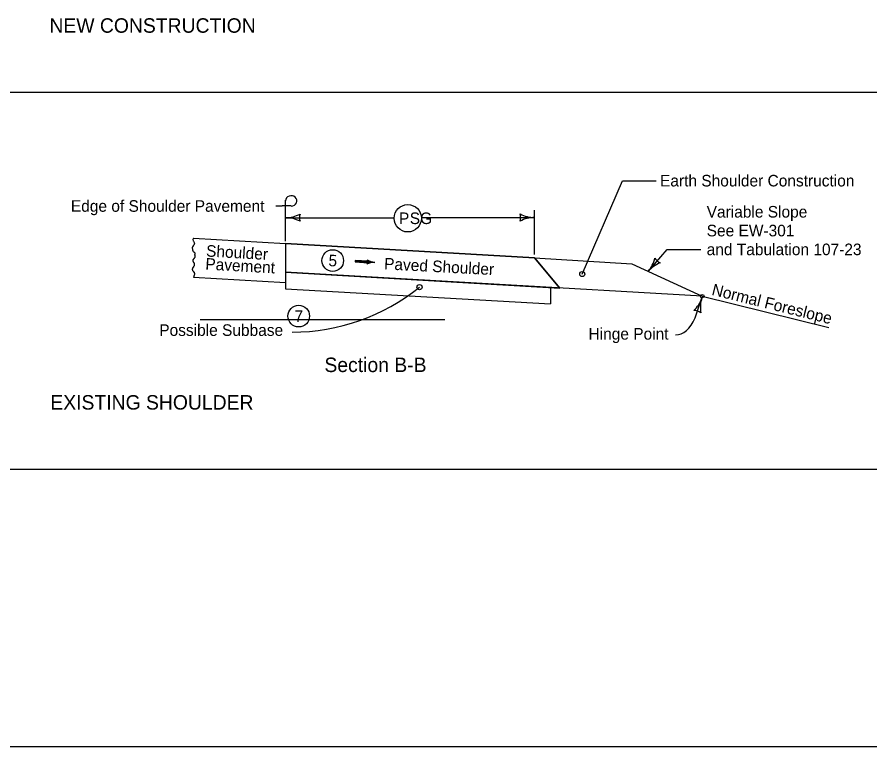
# Model space of a CAD drawing. Extents: x 6410 to 81668, y 3928 to 11667.
# Drawn here: x 11038 to 12218, y 7924 to 8933 of the extents above; entities that cross this region are included whole.
import ezdxf

# ---------------------------------------------------------------- set-up
doc = ezdxf.new("R2010")
doc.units = 0
for name, color, linetype in [('dsnCellElements', 7, 'Continuous'), ('dsnNonPlotable', 7, 'Continuous'), ('dsnShtPlotShapeBatchPrint', 7, 'Continuous'), ('dsnStdBlockModified', 7, 'Continuous'), ('Level 11', 7, 'Continuous'), ('Level 14', 7, 'Continuous'), ('Level 7', 7, 'Continuous'), ('Level 8', 7, 'Continuous')]:
    doc.layers.add(name, color=color, linetype=linetype)

msp = doc.modelspace()

# ---------------------------------------------------------------- linework, layer by layer
at = {"layer": 'dsnCellElements'}
for p, q in [((11819.9, 8577.8), (11875.6, 8706.9)), ((11875.6, 8706.9), (11922, 8706.9)), ((11396.3, 8671.9), (11405, 8671.9)), ((11417.5, 8671.9), (11405, 8671.9)), ((11409.7, 8659.1), (11409.7, 8679.9)), ((11409.7, 8623.1), (11409.7, 8659.1)), ((11910.9, 8581.5), (11937.5, 8611.9)), ((11937.5, 8611.9), (11983.9, 8611.9)), ((11524, 8594.5), (11505.8, 8595.5)), ((11523.9, 8593.5), (11523.9, 8593.5)), ((11524, 8595.5), (11524, 8595.5)), ((11976, 8517.2), (11985.5, 8544.8))]:
    msp.add_line(p, q, dxfattribs=at)
for points in [[(11524, 8595.4), (11505.8, 8596.5), (11505.7, 8594.6), (11523.9, 8593.5), (11523.9, 8595.1), (11506, 8596.2), (11506, 8594.7), (11523.5, 8593.8), (11523.6, 8594.9), (11506.3, 8596), (11506.2, 8595), (11523.3, 8594), (11523.4, 8594.7), (11506.5, 8595.8), (11506.4, 8595.2), (11523, 8594.3)], [(11523.6, 8596.7), (11524.3, 8595.5), (11524.3, 8593.9), (11523.5, 8592.5), (11526.2, 8593.3), (11529.4, 8594), (11530.3, 8594.1), (11528.1, 8594.7), (11524.9, 8595.9), (11523.9, 8596.4), (11524.1, 8592.9), (11529, 8594.1), (11524.4, 8595.7), (11524.4, 8593.3), (11527.8, 8594.2), (11524.8, 8595.1), (11524.5, 8593.7), (11526.7, 8594.2), (11525.1, 8594.7), (11525, 8594), (11525.8, 8594.2)]]:
    msp.add_lwpolyline(points, dxfattribs=at)
for centre, radius, start, end in [((11878.9, 8609.5), 42.5, 318.8454, 346.9178), ((11934.4, 8608.3), 16.4, 211.112, 246.5787), ((11942.9, 8553.5), 42.5, 110.7729, 138.8454), ((11945.3, 8558.6), 42.5, 312.9788, 341.0513), ((12025.7, 8531), 42.5, 161.0513, 189.1238), ((11973.9, 8511.1), 16.4, 53.3179, 88.7846)]:
    msp.add_arc(centre, radius, start, end, dxfattribs=at)
for centre, major_axis, ratio, start_param, end_param in [((11417.5, 8679), (-7.81, 0), 0.913811, 1.570796, 6.283185), ((11520.2, 8594.7), (3.88, 0), 0.913811, 5.202895, 7.237436), ((11532.5, 8573.7), (22.2, 0), 0.913811, 1.537172, 2.061295), ((11535.3, 8614.1), (-22.2, 0), 0.913811, 0.954258, 1.478381), ((11948.9, 8555.1), (0, 61.5), 0.559383, 3.141593, 4.048985)]:
    msp.add_ellipse(centre, major_axis=major_axis, ratio=ratio, start_param=start_param, end_param=end_param, dxfattribs=at)
at = {"layer": 'dsnNonPlotable'}
msp.add_line((10153.2, 8307.9), (13248.9, 8307.9), dxfattribs=at)
at = {"layer": 'dsnShtPlotShapeBatchPrint'}
for p, q in [((11754, 8604.6), (11754, 8666.3)), ((11409.7, 8655.7), (11559.7, 8655.7)), ((11597.5, 8655.9), (11754, 8655.9))]:
    msp.add_line(p, q, dxfattribs=at)
msp.add_circle((11578.6, 8654.9), 18.9, dxfattribs=at)
for centre, radius, start, end in [((11409.7, 8698.2), 42.5, 270, 298.0725), ((11445.3, 8655.7), 16.4, 162.2666, 197.7334), ((11718.3, 8655.9), 16.4, 342.2666, 17.7333), ((11754, 8698.4), 42.5, 241.9275, 270), ((11409.7, 8613.2), 42.5, 61.9275, 90), ((11754, 8613.4), 42.5, 90, 118.0725), ((11418.2, 8779.5), 282, 270.132, 308.7946)]:
    msp.add_arc(centre, radius, start, end, dxfattribs=at)
at = {"layer": 'dsnStdBlockModified'}
for p, q in [((11282.2, 8627.4), (11409.7, 8620)), ((11409.7, 8620), (11409.7, 8566)), ((11409.7, 8620), (11754, 8600)), ((11754, 8600), (11409.7, 8620)), ((11409.7, 8620), (11409.7, 8580.4)), ((11753.5, 8600.2), (11753.5, 8600.2)), ((11754, 8600), (11789, 8558.5)), ((11754, 8600), (11888.7, 8591.7)), ((11789, 8558.5), (11754, 8600)), ((11888.7, 8591.7), (11985.8, 8547.2)), ((11985.8, 8547.2), (11409.7, 8580.4)), ((11409.7, 8580.4), (11789, 8558.5)), ((11282.2, 8573.4), (11409.7, 8566)), ((11409.7, 8566), (11409.7, 8557.5)), ((11776.2, 8573.7), (11776.2, 8573.7)), ((11409.7, 8557.5), (11776.2, 8536.4)), ((11776.2, 8559.2), (11776.2, 8536.4)), ((11985.8, 8547.2), (12160.8, 8503.9)), ((11291.6, 8515.1), (11630.1, 8515.1))]:
    msp.add_line(p, q, dxfattribs=at)
msp.add_circle((11474.8, 8596.4), 15, dxfattribs=at)
msp.add_ellipse((11985.8, 8547.2), major_axis=(2.58, 0), ratio=0.913811, dxfattribs=at)
for points in [[(11282.2, 8627.4), (11281.7, 8623.8), (11282.8, 8622.3), (11283.6, 8620), (11283, 8617.9), (11281.1, 8615.6), (11280.6, 8613.7), (11281.1, 8611.4), (11282, 8609), (11283, 8608.3), (11284.4, 8605.7), (11284.4, 8604.9)], [(11282.4, 8587.8), (11282.6, 8588), (11282.8, 8588.3), (11283.2, 8588.8), (11283.5, 8589.4), (11283.6, 8589.7), (11283.7, 8590.1), (11283.8, 8590.7), (11283.9, 8591.3), (11283.8, 8591.9), (11283.8, 8592.2), (11283.7, 8592.3), (11283.7, 8592.4), (11283.5, 8592.8), (11283.2, 8593.2), (11282.9, 8593.5), (11282.6, 8593.9), (11282.5, 8594.2), (11282.4, 8594.5), (11282.1, 8595.1), (11281.9, 8595.6), (11281.8, 8595.9), (11281.8, 8596.2), (11281.8, 8596.4), (11281.8, 8596.5), (11281.9, 8597.3), (11282.1, 8597.8), (11282.4, 8598.3), (11282.8, 8598.9), (11283.3, 8599.5), (11283.9, 8600), (11284.1, 8600.3), (11284.3, 8600.7), (11284.5, 8601.1), (11284.6, 8601.6), (11284.8, 8602.1), (11284.8, 8602.3), (11284.8, 8602.4), (11284.8, 8602.6), (11284.8, 8603.1), (11284.6, 8603.6), (11284.6, 8603.7), (11284.5, 8603.8), (11284.5, 8604), (11284.4, 8604.1), (11284.4, 8604.9)], [(11282.4, 8587.8), (11282.2, 8587.5), (11282, 8587.3), (11281.7, 8587.1), (11281.5, 8586.8), (11281.4, 8586.5), (11281.3, 8586.2), (11281, 8585.7), (11280.9, 8585.4), (11280.8, 8585.1), (11280.7, 8584.8), (11280.7, 8584.6), (11280.7, 8584.5), (11280.7, 8584), (11280.8, 8583.5), (11281, 8583), (11281.3, 8582.4), (11281.7, 8581.8), (11282.3, 8581.3), (11282.8, 8580.7), (11283, 8580.4), (11283.2, 8580.1), (11283.6, 8579.1), (11283.7, 8578.6), (11283.7, 8578.2), (11283.7, 8577.9), (11283.6, 8577.6), (11283.6, 8577.3), (11283.5, 8577), (11283.2, 8575.9), (11283, 8575.3), (11282.8, 8574.7), (11282.6, 8574.1), (11282.5, 8573.8), (11282.3, 8573.5), (11282.2, 8573.4)]]:
    msp.add_spline(points, degree=3, dxfattribs=at)
at = {"layer": 'Level 11'}
msp.add_line((12308.8, 8828.9), (10153.2, 8828.9), dxfattribs=at)
at = {"layer": 'Level 14'}
for centre in [(11819.9, 8577.8), (11594.9, 8559.7)]:
    msp.add_circle(centre, 3.54, dxfattribs=at)
at = {"layer": 'Level 7'}
for centre in [(11474.8, 8596.4), (11427.8, 8519.7)]:
    msp.add_circle(centre, 15, dxfattribs=at)
at = {"layer": 'Level 8'}
msp.add_lwpolyline([(10132.5, 9944), (13267.5, 9944), (13267.5, 7924), (10132.5, 7924)], close=True, dxfattribs=at)

# ---------------------------------------------------------------- texts
at = {"layer": 'dsnCellElements'}
for s, height, p in [('NEW CONSTRUCTION', 20, (11083.1, 8911.4)), ('Earth Shoulder Construction', 16, (11927.5, 8698.9)), ('Edge of Shoulder Pavement', 16, (11112.8, 8663.9)), ('Variable Slope', 16, (11992, 8655.9)), ('See EW-301', 16, (11992, 8629.9)), ('and Tabulation 107-23', 16, (11992, 8603.9)), ('Possible Subbase', 16, (11235, 8492.3)), ('Hinge Point', 16, (11828.6, 8487.2)), ('Section B-B', 20, (11463.4, 8442.3)), ('EXISTING SHOULDER', 20, (11084.4, 8390.4))]:
    msp.add_text(s, height=height, dxfattribs=at).set_placement(p)
for s, rotation, p in [('Shoulder', 356.7346, (11299.4, 8602.1)), ('Pavement', 356.7346, (11298.4, 8584.1)), ('Paved Shoulder ', 356.983, (11545.6, 8584.3)), ('Normal Foreslope', 346.0988, (11998, 8549.2))]:
    msp.add_text(s, height=16, rotation=rotation, dxfattribs=at).set_placement(p)
at = {"layer": 'dsnShtPlotShapeBatchPrint'}
for s, p in [('P', (11566.5, 8646.9)), ('SG', (11581.4, 8646.9))]:
    msp.add_text(s, height=16, dxfattribs=at).set_placement(p)
at = {"layer": 'Level 7'}
msp.add_text('5', height=16, rotation=356.6997, dxfattribs=at).set_placement((11468.6, 8588.8))
msp.add_text('7', height=16, dxfattribs=at).set_placement((11422.1, 8511.7))

doc.saveas('drawing.dxf')
